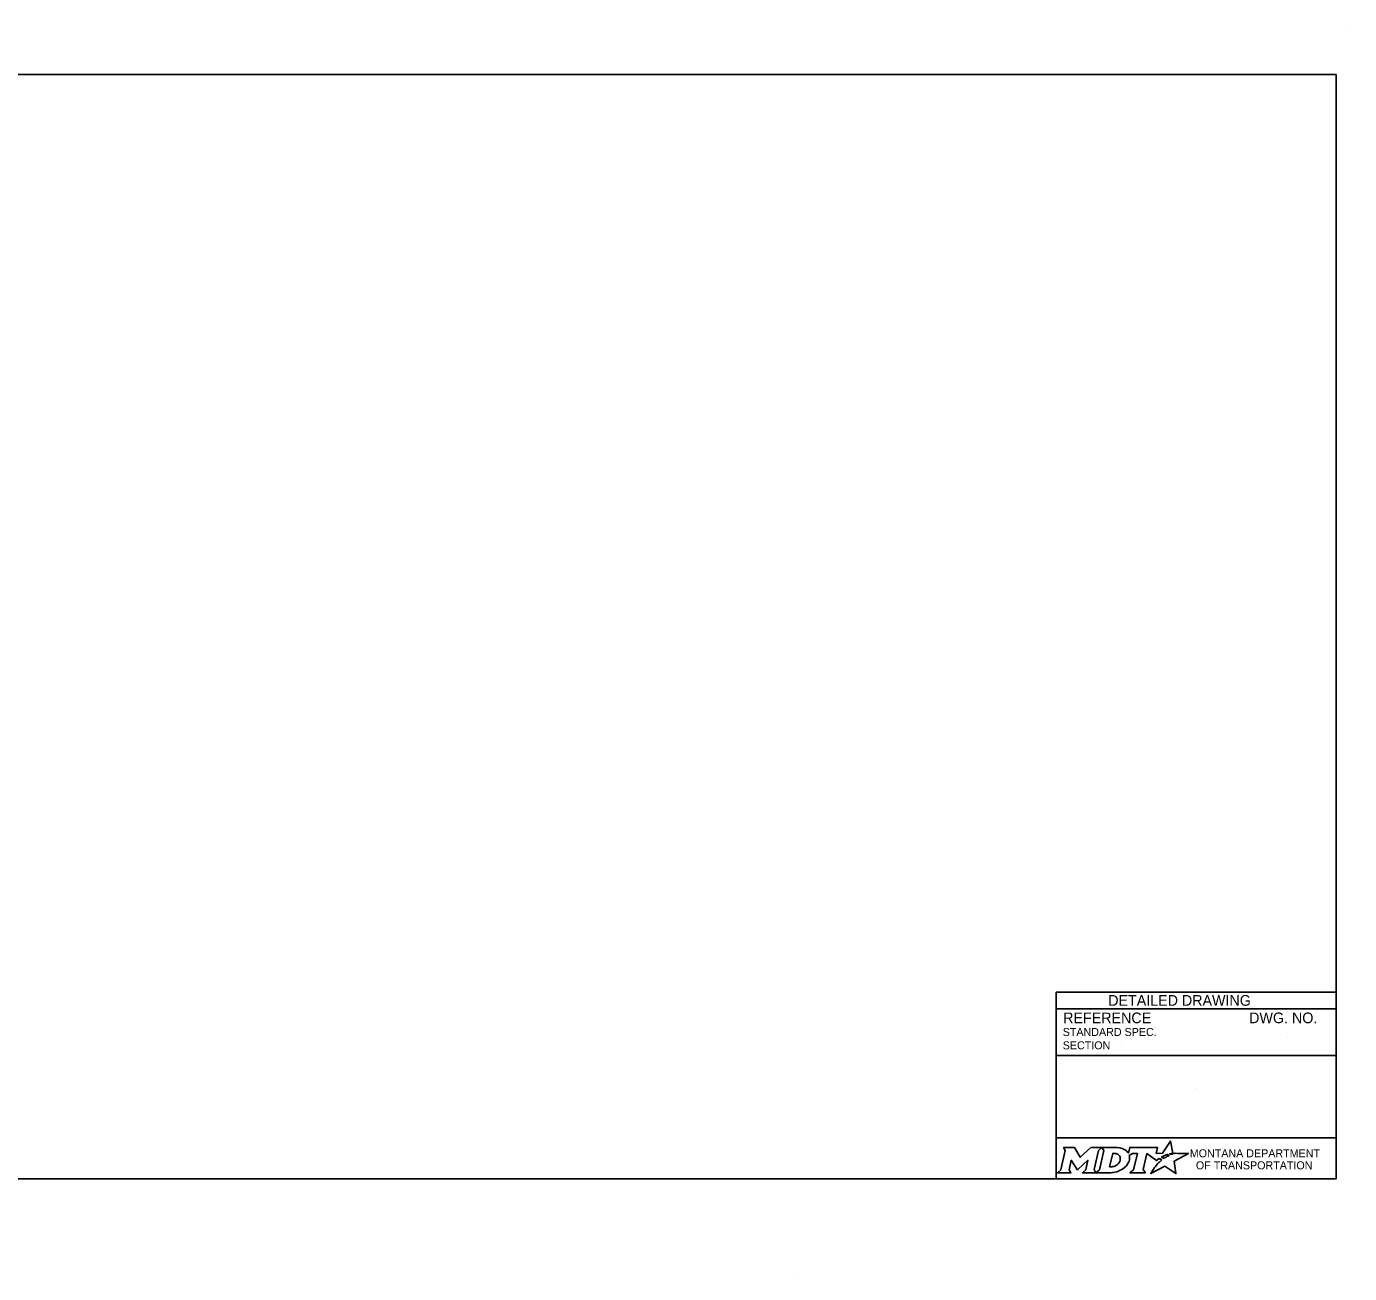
# Model space of a CAD drawing. Extents: x 49991.4 to 50021, y 49987.6 to 50011.4.
# Drawn here: x 50011.12 to 50021.04, y 49999.18 to 50008.52 of the extents above; entities that cross this region are included whole.
import ezdxf

# ---------------------------------------------------------------- set-up
doc = ezdxf.new("R2010")
doc.units = 0
for name, color, linetype in [('Default', 7, 'Continuous'), ('Level 1', 7, 'Continuous'), ('Level 4', 7, 'Continuous')]:
    doc.layers.add(name, color=color, linetype=linetype)

msp = doc.modelspace()

# ---------------------------------------------------------------- linework, layer by layer
at = {"layer": 'Default'}
for points in [[(50018.8933, 50000.1206), (50018.9074, 50000.0972), (50018.8739, 49999.9539), (50018.8482, 49999.9314), (50018.9498, 49999.9314), (50018.9363, 49999.9542), (50018.9525, 50000.0243), (50018.9962, 49999.9553), (50019.0015, 49999.9553), (50019.0766, 50000.0248), (50019.0602, 49999.9537), (50019.0355, 49999.9317), (50019.1371, 49999.9317), (50019.1233, 49999.955), (50019.1565, 50000.0974)], [(50019.1565, 50000.0974), (50019.1818, 50000.1206), (50019.0994, 50000.1206), (50019.0198, 50000.0476), (50018.9753, 50000.1203), (50018.8933, 50000.1206)], [(50019.2954, 50000.1206), (50019.1818, 50000.1206), (50019.1965, 50000.0977), (50019.1626, 49999.9539), (50019.1371, 49999.9317), (50019.2477, 49999.9317)], [(50019.7003, 50000.0679), (50019.69, 50000.0735), (50019.7016, 50000.0763), (50019.7132, 50000.0783), (50019.6958, 50000.1684), (50019.6363, 50000.0771), (50019.589, 50000.0764), (50019.5993, 50000.1205), (50019.3901, 50000.1206), (50019.38, 50000.0781), (50019.3742, 50000.0864)], [(50019.3194, 50000.0339), (50019.3182, 50000.0258), (50019.315, 50000.0165), (50019.3108, 50000.0083), (50019.3052, 50000.0008), (50019.2987, 49999.9939), (50019.2908, 49999.9876), (50019.2825, 49999.9829), (50019.2734, 49999.979), (50019.2643, 49999.9767), (50019.2551, 49999.9758), (50019.2392, 49999.9758), (50019.2628, 50000.0758), (50019.2788, 50000.0758), (50019.2864, 50000.0752), (50019.294, 50000.0733), (50019.3006, 50000.0703), (50019.3067, 50000.0661), (50019.3115, 50000.0611), (50019.3152, 50000.0551), (50019.3179, 50000.0489), (50019.3195, 50000.0415), (50019.3195, 50000.0385), (50019.3194, 50000.0339)], [(50019.3868, 50000.0615), (50019.4114, 50000.0746), (50019.4483, 50000.0746), (50019.4197, 49999.9541), (50019.3922, 49999.9314), (50019.5084, 49999.9314), (50019.4914, 49999.9543), (50019.5196, 50000.0745), (50019.5909, 50000.0228), (50019.612, 50000.0379), (50019.6317, 50000.027)], [(50019.5759, 49999.9711), (50019.5606, 49999.9467), (50019.5559, 49999.9392), (50019.5501, 49999.9306), (50019.5478, 49999.9263), (50019.6531, 49999.9794), (50019.737, 49999.9243), (50019.7239, 50000.017), (50019.8308, 50000.0754), (50019.7815, 50000.0762), (50019.7514, 50000.0766), (50019.7306, 50000.0769), (50019.7238, 50000.0754), (50019.7189, 50000.0742), (50019.7105, 50000.0719), (50019.7003, 50000.0679)], [(50019.6499, 50000.0403), (50019.6475, 50000.0386), (50019.6292, 50000.0482), (50019.6395, 50000.0539), (50019.6436, 50000.0561), (50019.6522, 50000.0601), (50019.6579, 50000.0627), (50019.6658, 50000.0657), (50019.6731, 50000.0684), (50019.6849, 50000.061), (50019.6809, 50000.0589), (50019.6763, 50000.0564), (50019.6721, 50000.0542), (50019.6671, 50000.0513), (50019.6652, 50000.0502), (50019.6625, 50000.0486), (50019.66, 50000.0472), (50019.6577, 50000.0456), (50019.6551, 50000.0438), (50019.6524, 50000.042), (50019.6499, 50000.0403)], [(50019.2934, 49999.939), (50019.3018, 49999.9416), (50019.3148, 49999.947), (50019.3352, 49999.958)], [(50019.5898, 49999.9872), (50019.5898, 49999.9872)]]:
    msp.add_lwpolyline(points, dxfattribs=at)
for centre, radius, start, end in [((50019.2745, 50000.0595), 0.1183, 300.91025, 339.13831), ((50019.3185, 50000.0422), 0.0709, 339.53292, 15.85821)]:
    msp.add_arc(centre, radius, start, end, dxfattribs=at)
for centre, major_axis, ratio, start_param, end_param in [((50019.2933, 50000.0732), (0.0834, -0.0037), 0.568097, 0.61298, 1.570796), ((50019.3489, 50000.0805), (0.0361, -0.0295), 0.469099, 1.225588, 1.570796), ((50019.5996, 49999.9974), (-0.0098, -0.0102), 0.016458, 3.141593, 6.279097), ((50019.6206, 50000.0173), (-0.0112, -0.0097), 0.021651, 3.157348, 6.283185), ((50019.248, 50000.08), (0, 0.1484), 0.987302, 3.139398, 3.456847), ((50019.5829, 49999.9791), (-0.00694, -0.00806), 0.008222, 0, 3.137361)]:
    msp.add_ellipse(centre, major_axis=major_axis, ratio=ratio, start_param=start_param, end_param=end_param, dxfattribs=at)
at = {"layer": 'Level 1'}
for p, q in [((50021.0378, 50008.5236), (50021.0378, 50008.5236)), ((50016.9001, 49999.1756), (50016.9001, 49999.1756))]:
    msp.add_line(p, q, dxfattribs=at)
msp.add_lwpolyline([(50020.9378, 50008.1646), (50009.7374, 50008.1646), (50009.7374, 49999.8856), (50020.9378, 49999.8856)], close=True, dxfattribs=at)
at = {"layer": 'Level 4'}
for p, q in [((50020.9378, 50001.2856), (50018.8378, 50001.2856)), ((50018.8378, 50001.2856), (50018.8378, 49999.8856)), ((50020.9378, 50001.1606), (50018.8378, 50001.1606)), ((50019.3321, 50000.8861), (50019.3321, 50000.8861)), ((50020.5739, 50000.9455), (50020.5739, 50000.9455)), ((50020.9378, 50000.8106), (50018.8378, 50000.8106)), ((50019.8878, 50000.5615), (50019.8878, 50000.5615)), ((50020.9378, 50000.1925), (50018.8378, 50000.1925))]:
    msp.add_line(p, q, dxfattribs=at)

# ---------------------------------------------------------------- texts
at = {"layer": 'Default'}
for s, p in [('MONTANA DEPARTMENT', (50019.8403, 50000.0468)), ('OF TRANSPORTATION', (50019.8862, 49999.9568))]:
    msp.add_text(s, height=0.06, rotation=360, dxfattribs=at).set_placement(p)
at = {"layer": 'Level 4'}
for s, height, p in [('DETAILED DRAWING', 0.0799, (50019.2295, 50001.1831)), ('REFERENCE', 0.08, (50018.8914, 50001.0522)), ('DWG. NO.', 0.08, (50020.2856, 50001.0522)), ('STANDARD SPEC.', 0.06, (50018.8881, 50000.9562)), ('SECTION', 0.06, (50018.8881, 50000.8562))]:
    msp.add_text(s, height=height, dxfattribs=at).set_placement(p)

doc.saveas('drawing.dxf')
